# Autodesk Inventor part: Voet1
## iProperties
Created: 2007-06
Part Number: Voet1
Material: Steel
Document SubType Name: Modeling
Designer: Phil Trethewie
Author: Phil Trethewie
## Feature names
1. Sweep1
